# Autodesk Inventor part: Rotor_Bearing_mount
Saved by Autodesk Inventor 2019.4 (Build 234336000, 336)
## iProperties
Created: 2020-04
Part Number: Rotor_Bearing_mount
Material: Generic
Document SubType Name: Modeling
Designer: Administrator
Density: 1 g/cm^3
Appearance: Default
Title: Rotor_Bearing_mount v5
Author: Administrator
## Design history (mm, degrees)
feature "Body3"
body "Solid1"
